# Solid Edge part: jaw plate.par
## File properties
Title: Jaw Plate
Author: Abhinav
Template: Normal.par
Last saved by: CADCIM
Revision: 8
Application: Solid Edge
Density: 0.0000078 kg/mm^3
Accuracy: 0.01
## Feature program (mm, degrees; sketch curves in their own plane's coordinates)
sketch for "unnamed Protrusion 1" plane through (0, 0, 0) normal (0, -1, 0) x-axis (1, 0, 0)
  line (-34.925, 22.225) -> (34.925, 22.225)
  line (34.925, 22.225) -> (34.925, -22.225)
  line (34.925, -22.225) -> (-34.925, -22.225)
  line (-34.925, -22.225) -> (-34.925, 22.225)
extrude "unnamed Protrusion 1" add finite 4.7498 symmetric
sketch for "Hole_1" plane through (0, -2.3749, 0) normal (0, -1, 0) x-axis (1, 0, 0)
  hole centre (19.05, 3.175) bore radius 3.175
hole "Hole_1" diameter 6.35 through
sketch for "unnamed Hole 1" plane through (0, -2.3749, 0) normal (0, -1, 0) x-axis (1, 0, 0)
  hole centre (-19.05, 3.175) bore radius 3.175
  dimension (linear) = 19.05
  dimension (linear) = 19.05
hole "unnamed Hole 1" through
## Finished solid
Body 1: solid body, 6 faces, 12 edges, 8 vertices.
  Faces by surface: plane 6
  Edges by curve: line 12
Bounding box of the edges (mm): 69.850 x 4.750 x 44.450, from (-34.925, -2.3749, -22.225) to (34.925, 2.3749, 22.225).
Planar faces by outward normal: +x 1, +y 1, +z 1, -x 1, -y 1, -z 1
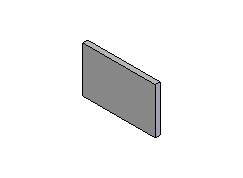
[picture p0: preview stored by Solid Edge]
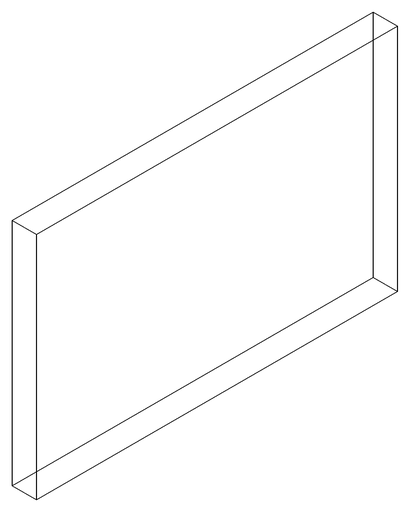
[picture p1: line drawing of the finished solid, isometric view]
